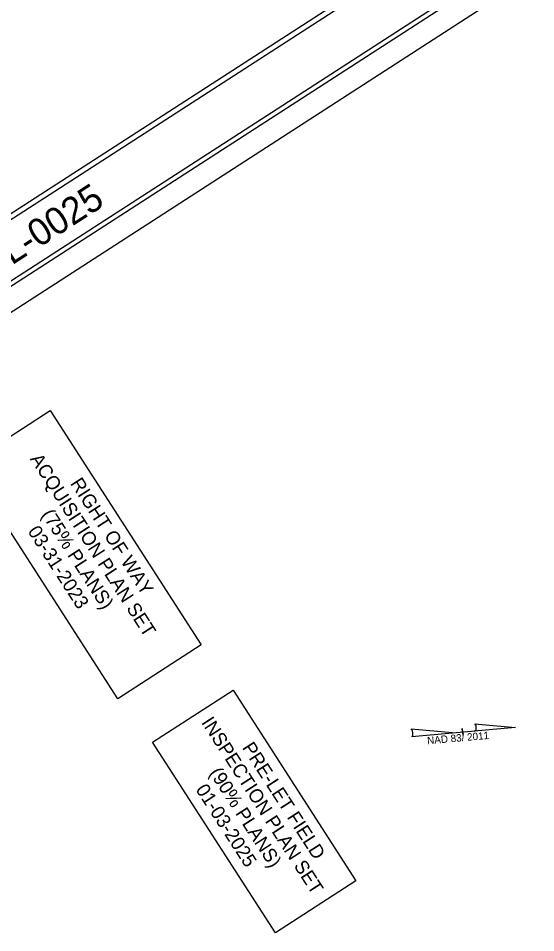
# Model space of a CAD drawing. Extents: x 2160312 to 2162215, y 789569 to 792090.
# Drawn here: x 2161620 to 2162215, y 789569 to 790620 of the extents above; entities that cross this region are included whole.
import ezdxf

# ---------------------------------------------------------------- set-up
doc = ezdxf.new("R2010")
doc.units = 0
for name, color, linetype in [('Default', 7, 'Continuous'), ('DEV TITLE SHEET CELL', 7, 'Continuous'), ('Sheet Plot Border Outside CELL', 7, 'Continuous'), ('Sheet Sticker Incomplete CELL', 7, 'Continuous')]:
    doc.layers.add(name, color=color, linetype=linetype)

msp = doc.modelspace()

# ---------------------------------------------------------------- linework, layer by layer
at = {"layer": 'Default'}
for p, q in [((2162191.9, 789804.9), (2162144.3, 789800.7)), ((2162145, 789809.1), (2162191.9, 789805)), ((2162191.9, 789804.9), (2162191.9, 789805)), ((2162191.9, 789804.9), (2162191.9, 789805)), ((2162119.6, 789798.6), (2162071.8, 789802.8)), ((2162072.7, 789794.4), (2162119.6, 789798.6)), ((2162119.6, 789798.6), (2162145.7, 789800.9)), ((2162131.1, 789800), (2162130.8, 789803.6)), ((2162130.8, 789803.6), (2162130.8, 789803.6)), ((2162130.8, 789803.5), (2162131.5, 789795.5)), ((2162144.3, 789800.7), (2162145.7, 789800.9))]:
    msp.add_line(p, q, dxfattribs=at)
for centre, start_param, end_param in [((2162144.9, 789804.9), 0.216388, 2.908219), ((2162072, 789798.5), 0.201328, 3.141593)]:
    msp.add_ellipse(centre, major_axis=(0.34, -4.22), ratio=0.461098, start_param=start_param, end_param=end_param, dxfattribs=at)
at = {"layer": 'DEV TITLE SHEET CELL'}
for p, q in [((2162129.9, 790729.8), (2161273.7, 790177.1)), ((2161276.7, 790172.3), (2162132.9, 790725)), ((2161307.1, 790115.5), (2162172, 790673.7)), ((2161385.3, 790172), (2162164.9, 790675.3))]:
    msp.add_line(p, q, dxfattribs=at)
at = {"layer": 'Sheet Plot Border Outside CELL'}
msp.add_lwpolyline([(2160375.6, 791493.5), (2161291, 790075.3), (2162215.2, 790671.9), (2161299.7, 792090.1)], close=True, dxfattribs=at)
at = {"layer": 'Sheet Sticker Incomplete CELL'}
for points in [[(2161560.9, 790107.2), (2161656.6, 790169), (2161830.5, 789899.7), (2161734.7, 789837.9)], [(2161774.5, 789787.9), (2161867.1, 789847.6), (2162008.4, 789628.8), (2161915.8, 789569)]]:
    msp.add_lwpolyline(points, close=True, dxfattribs=at)

# ---------------------------------------------------------------- texts
at = {"layer": 'Default'}
msp.add_text('NAD 83/ 2011', height=8.5, rotation=5.0082, dxfattribs=at).set_placement((2162090.7, 789785.5))
at = {"layer": 'DEV TITLE SHEET CELL'}
msp.add_text('TIP PROJECT: HL-0025', height=31, rotation=32.8434, dxfattribs=at).set_placement((2161341.7, 790160.7))
at = {"layer": 'Sheet Sticker Incomplete CELL'}
for s, height, p in [('ACQUISITION PLAN SET', 15.792, (2161633.1, 790113.4)), ('RIGHT OF WAY ', 15.792, (2161679.4, 790085.4)), ('(75% PLANS)', 15.792, (2161646.2, 790049.5)), ('03-31-2023', 15.79, (2161630.4, 790030.3)), ('INSPECTION PLAN SET', 15.792, (2161830.1, 789810.7)), ('PRE-LET FIELD', 15.792, (2161877, 789781.7)), ('(90% PLANS)', 15.792, (2161839.3, 789752.7)), ('01-03-2025', 15.79, (2161823.5, 789733.5))]:
    msp.add_text(s, height=height, rotation=302.8433, dxfattribs=at).set_placement(p)

doc.saveas('drawing.dxf')
